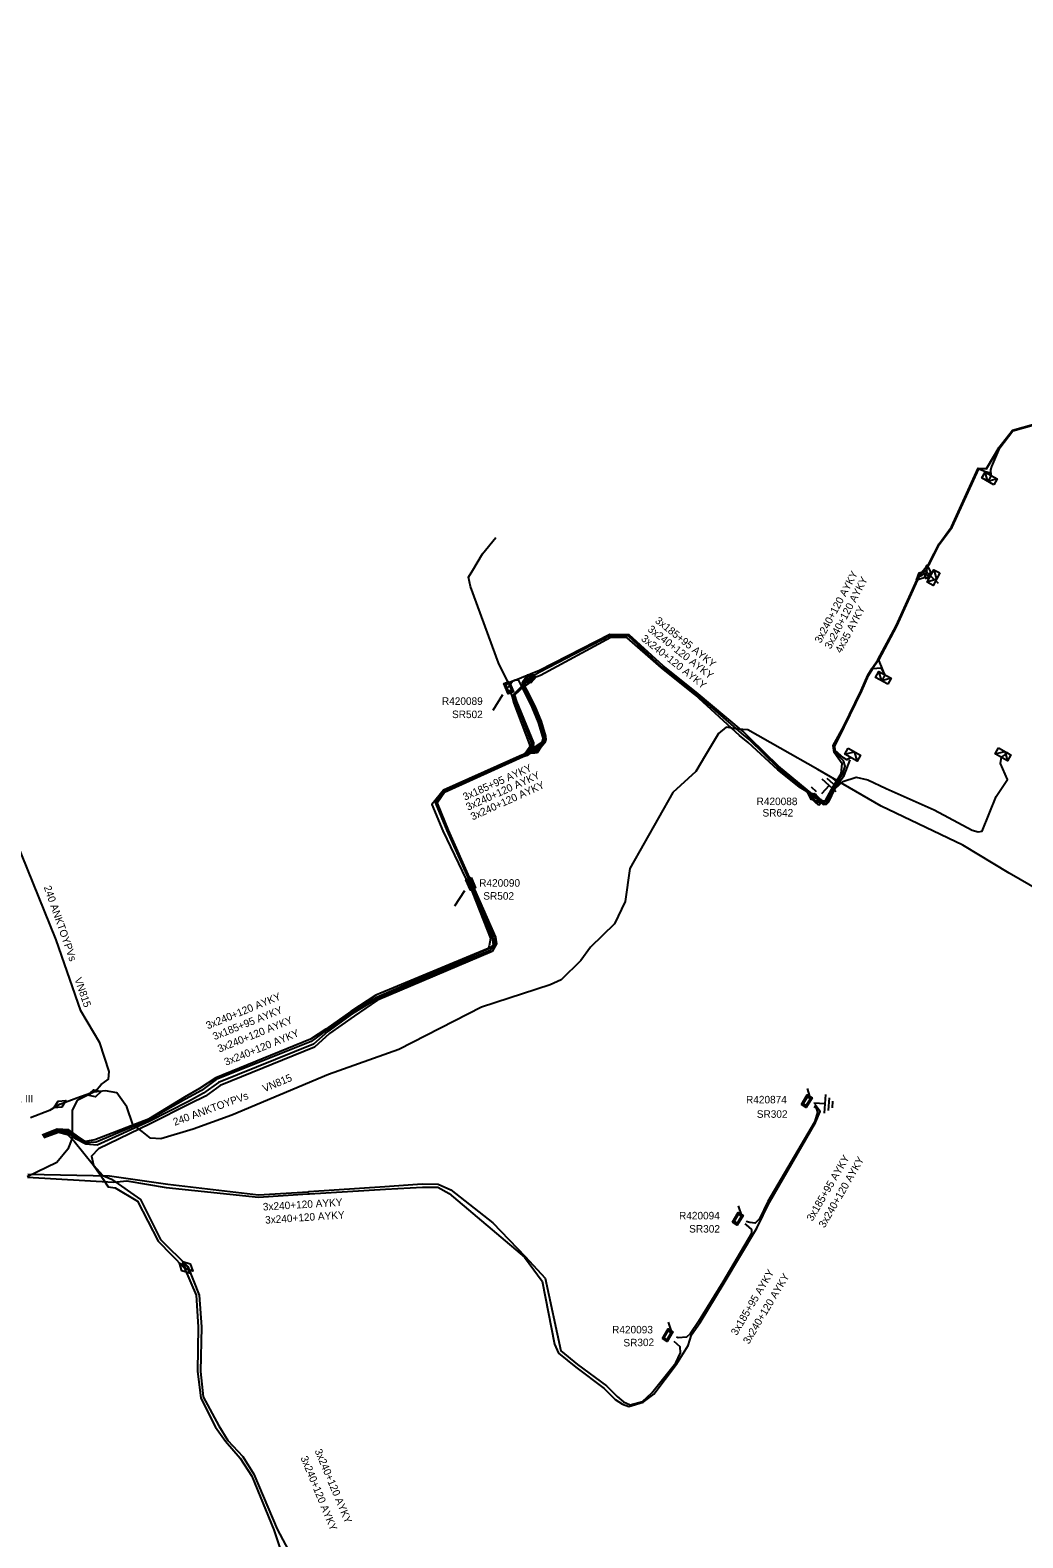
# Model space of a CAD drawing. Extents: x -540028 to -538776, y -1157064 to -1155670.
# Drawn here: x -539454.6 to -539322.6, y -1155928.9 to -1155728.4 of the extents above; entities that cross this region are included whole.
import ezdxf

# ---------------------------------------------------------------- set-up
doc = ezdxf.new("R2010")
doc.units = 0
for name, color, linetype in [('Vrstva 15', 7, 'Continuous'), ('Vrstva 19', 7, 'Continuous'), ('Vrstva 2', 7, 'Continuous'), ('Vrstva 27', 7, 'Continuous'), ('Vrstva 28', 7, 'Continuous'), ('Vrstva 29', 7, 'Continuous'), ('Vrstva 30', 7, 'Continuous'), ('Vrstva 31', 7, 'Continuous'), ('Vrstva 5', 7, 'Continuous'), ('Vrstva 52', 7, 'Continuous'), ('Vrstva 59', 7, 'Continuous'), ('Vrstva 6', 7, 'Continuous'), ('Vrstva 7', 7, 'Continuous'), ('Vrstva 9', 7, 'Continuous')]:
    doc.layers.add(name, color=color, linetype=linetype)

# ---------------------------------------------------------------- blocks, each defined once
blk = doc.blocks.new('17')
at = {"layer": 'Vrstva 2'}
blk.add_lwpolyline([(-1.875, 0), (0, 0.9375), (1.875, 0), (0, -0.9375)], close=True, dxfattribs=at)
blk = doc.blocks.new('132')
at = {"layer": 'Vrstva 2'}
for points in [[(-1.5, 1.5), (1.5, 1.5), (1.5, 0), (-1.5, 0)], [(-1.1, 1.2), (1.1, 1.2), (1.1, 0.3), (-1.1, 0.3)]]:
    blk.add_lwpolyline(points, close=True, dxfattribs=at)
blk = doc.blocks.new('23')
at = {"layer": 'Vrstva 2'}
blk.add_lwpolyline([(1.875, -1.8), (-1.875, -1.8), (-1.875, 0), (1.875, 0)], close=True, dxfattribs=at)
blk.add_lwpolyline([(1.875, 0), (0, -1.8), (-1.875, 0)], dxfattribs=at)
blk = doc.blocks.new('11')
at = {"layer": 'Vrstva 2'}
for p, q in [((0, -4.3), (0, -1.3)), ((-2.5, -4.3), (2.5, -4.3)), ((-1.7, -5.3), (1.7, -5.3)), ((-0.9, -6.3), (0.9, -6.3))]:
    blk.add_line(p, q, dxfattribs=at)

msp = doc.modelspace()

# ---------------------------------------------------------------- linework, layer by layer
at = {"layer": 'Vrstva 5'}
for points in [[(-539450.64, -1155871.22), (-539448.38, -1155870.37), (-539445.91, -1155869.51), (-539445.16, -1155868.63), (-539444.2, -1155867.88), (-539444.08, -1155866.88), (-539445.32, -1155863.06), (-539447.87, -1155858.8), (-539451.16, -1155849.36), (-539456.5, -1155836.11), (-539463.8, -1155817.93), (-539469.08, -1155806.9), (-539474.9, -1155790.51), (-539482.11, -1155775.46), (-539488.3, -1155760.82), (-539493.72, -1155747.89), (-539499.46, -1155736.84), (-539501.89, -1155728.36)], [(-539350.46, -1155830.35), (-539349.58, -1155830.73), (-539349.23, -1155830.93), (-539348.81, -1155830.82), (-539348.05, -1155829.35), (-539346.75, -1155827.26), (-539346.61, -1155825.96), (-539347.7, -1155824.44), (-539347.79, -1155823.53), (-539346.43, -1155821.03), (-539344.08, -1155816.21), (-539343.22, -1155814.17), (-539342.63, -1155813.23), (-539341.85, -1155812.12), (-539339.44, -1155807.59), (-539336.43, -1155800.94), (-539335.03, -1155799.25), (-539333.73, -1155796.7), (-539332.06, -1155794.44), (-539328.52, -1155786.63), (-539327.44, -1155786.68), (-539325.72, -1155783.84), (-539323.97, -1155781.59), (-539321.14, -1155780.78)], [(-539349.17, -1155830.8), (-539349.17, -1155830.84), (-539349, -1155831.04), (-539348.87, -1155831.01), (-539347.97, -1155829.36), (-539346.58, -1155827.35), (-539346.21, -1155826.25), (-539346.44, -1155825.57), (-539346.82, -1155825.15), (-539347.63, -1155824.37), (-539347.67, -1155823.56), (-539346.39, -1155821.05), (-539344.03, -1155816.24), (-539343.17, -1155814.19), (-539342.59, -1155813.26), (-539341.81, -1155812.15), (-539339.4, -1155807.61), (-539336.39, -1155800.97), (-539334.99, -1155799.28), (-539333.69, -1155796.73), (-539332.02, -1155794.47), (-539328.48, -1155786.68), (-539327.41, -1155786.73), (-539325.68, -1155783.87), (-539323.94, -1155781.64), (-539321.12, -1155780.82)], [(-539335.35, -1155800.45), (-539335.32, -1155799.75), (-539334.95, -1155799.31), (-539333.65, -1155796.75), (-539331.98, -1155794.49), (-539328.45, -1155786.73), (-539327.56, -1155787.08), (-539327.05, -1155787.19), (-539326.8, -1155787.6), (-539326.85, -1155786.84), (-539326.71, -1155786.39), (-539325.64, -1155783.9), (-539323.91, -1155781.68), (-539321.1, -1155780.87)], [(-539345.45, -1155825.13), (-539345.98, -1155825.42), (-539346.44, -1155825.18), (-539347.53, -1155824.18), (-539347.58, -1155823.6), (-539346.34, -1155821.07), (-539343.99, -1155816.26), (-539343.13, -1155814.22), (-539342.55, -1155813.29), (-539341.47, -1155813.2), (-539340.92, -1155814.12), (-539341.38, -1155813.02), (-539341.76, -1155812.18), (-539339.35, -1155807.63), (-539336.34, -1155800.99), (-539336.03, -1155800.89)], [(-539336.03, -1155800.89), (-539335.81, -1155800.7), (-539334.86, -1155800.96), (-539335.35, -1155800.45)], [(-539350.17, -1155830.06), (-539350.29, -1155830.09), (-539350.5, -1155830.02), (-539355.08, -1155826.25), (-539358.89, -1155822.53), (-539359.8, -1155821.67), (-539366.01, -1155816.43), (-539370.42, -1155812.91), (-539374.94, -1155808.8), (-539377.53, -1155808.75), (-539386.87, -1155813.56), (-539390.47, -1155814.99), (-539390.96, -1155815.66), (-539391.31, -1155815.93)], [(-539350.06, -1155830.15), (-539350.27, -1155830.21), (-539350.61, -1155830.16), (-539355.12, -1155826.47), (-539358.99, -1155822.71), (-539360.01, -1155821.86), (-539366.13, -1155816.57), (-539370.58, -1155813.08), (-539375.01, -1155808.97), (-539377.49, -1155808.93), (-539386.81, -1155813.78), (-539388.26, -1155814.55)], [(-539350.46, -1155830.35), (-539351.41, -1155829.57), (-539352.28, -1155829.08), (-539355.17, -1155826.74), (-539359.13, -1155823.11), (-539360.25, -1155822.19), (-539366.15, -1155816.77), (-539370.64, -1155813.2), (-539375.21, -1155809.19), (-539377.37, -1155809.14), (-539386.75, -1155814.19), (-539388.18, -1155814.73)], [(-539387.94, -1155824.06), (-539386.71, -1155823.21), (-539386.48, -1155822.94), (-539386.38, -1155822.64), (-539386.4, -1155822.37), (-539386.99, -1155820.48), (-539387.82, -1155818.43), (-539388.91, -1155816.28), (-539389.26, -1155815.6), (-539389.63, -1155814.88), (-539390.08, -1155814.81), (-539391.43, -1155815.38), (-539391.2, -1155816.18)], [(-539387.77, -1155824.15), (-539386.58, -1155823.36), (-539386.3, -1155823.04), (-539386.18, -1155822.67), (-539386.2, -1155822.33), (-539386.8, -1155820.41), (-539387.64, -1155818.35), (-539388.73, -1155816.19), (-539389.08, -1155815.51), (-539389.11, -1155815.09), (-539388.87, -1155814.81), (-539388.26, -1155814.55)], [(-539387.42, -1155824.07), (-539386.45, -1155823.51), (-539386.12, -1155823.14), (-539385.98, -1155822.7), (-539386, -1155822.29), (-539386.61, -1155820.34), (-539387.46, -1155818.27), (-539388.55, -1155816.1), (-539388.95, -1155815.32), (-539388.93, -1155815.17), (-539388.75, -1155814.97), (-539388.18, -1155814.73)], [(-539314.79, -1155846.05), (-539324.41, -1155840.48), (-539330.57, -1155836.78), (-539341.42, -1155831.6), (-539349.86, -1155826.71), (-539354.84, -1155823.88), (-539359.14, -1155821.43), (-539360.48, -1155821.33), (-539362.03, -1155821.08), (-539363.05, -1155821.91), (-539364.77, -1155824.8), (-539366.07, -1155826.96), (-539369.12, -1155829.77), (-539374.87, -1155839.9), (-539375.46, -1155844.26), (-539376.91, -1155847.22), (-539380.1, -1155850.36), (-539381.37, -1155852.1), (-539383.98, -1155854.67), (-539385.45, -1155855.37), (-539394.59, -1155858.34), (-539405.57, -1155863.94), (-539414.91, -1155867.28), (-539427.79, -1155872.68), (-539432.92, -1155874.55), (-539437.2, -1155875.84), (-539438.59, -1155875.77), (-539439.7, -1155874.86), (-539440.93, -1155873.95), (-539441.75, -1155871.58), (-539443.09, -1155869.72), (-539444.57, -1155869.47), (-539446.14, -1155869.63)], [(-539387.77, -1155824.15), (-539388.62, -1155824.67), (-539389.09, -1155824.87), (-539399.57, -1155829.62), (-539400.71, -1155831.18), (-539399.19, -1155834.82), (-539395.58, -1155842.86), (-539392.98, -1155849.03), (-539392.74, -1155849.96), (-539393.44, -1155850.79), (-539408.48, -1155857.21), (-539411.79, -1155859.23), (-539415.03, -1155861.58), (-539416.93, -1155863.25), (-539429.55, -1155868.34), (-539431.54, -1155869.77), (-539433.56, -1155870.87), (-539438.76, -1155873.53), (-539445.67, -1155876.69), (-539447.18, -1155876.55), (-539448.46, -1155875.9), (-539449.51, -1155875.09), (-539450.89, -1155874.8), (-539452.86, -1155875.56)], [(-539387.94, -1155824.06), (-539388.72, -1155824.5), (-539389.11, -1155824.74), (-539399.64, -1155829.45), (-539401.18, -1155831.35), (-539399.72, -1155834.88), (-539396.61, -1155841.35), (-539396.58, -1155841.48)], [(-539387.42, -1155824.07), (-539388.52, -1155824.84), (-539389.02, -1155825.03), (-539399.51, -1155829.78), (-539400.48, -1155831.19), (-539398.99, -1155834.79), (-539395.86, -1155841.89)], [(-539349.33, -1155830.76), (-539349.26, -1155831.05), (-539348.95, -1155831.28), (-539348.65, -1155831.17), (-539347.78, -1155829.42), (-539346.35, -1155827.51), (-539345.56, -1155825.42)], [(-539396.15, -1155842.49), (-539395.96, -1155842.66), (-539395.83, -1155842.97), (-539393.4, -1155849.2), (-539393.54, -1155850.15), (-539393.7, -1155850.5), (-539408.62, -1155856.73), (-539411.96, -1155858.9), (-539415.3, -1155861.26), (-539417.31, -1155862.58), (-539429.92, -1155867.72), (-539432.06, -1155869.16), (-539434.06, -1155870.29), (-539438.88, -1155873.23), (-539445.99, -1155875.96), (-539447.23, -1155876.18), (-539448.29, -1155875.49), (-539449.45, -1155874.63), (-539450.99, -1155874.53), (-539453, -1155875.33)], [(-539395.86, -1155841.89), (-539395.76, -1155842.59), (-539393.14, -1155849.05), (-539393.04, -1155850.05), (-539393.58, -1155850.57), (-539408.56, -1155857.02), (-539411.88, -1155859.03), (-539415.22, -1155861.43), (-539417.23, -1155862.88), (-539429.85, -1155867.93), (-539431.8, -1155869.43), (-539433.94, -1155870.58), (-539438.85, -1155873.36), (-539445.81, -1155876.26), (-539447.2, -1155876.38), (-539448.34, -1155875.72), (-539449.5, -1155874.86), (-539450.95, -1155874.64), (-539452.93, -1155875.46)], [(-539396.31, -1155842.12), (-539395.5, -1155842.69), (-539392.72, -1155849), (-539392.57, -1155849.91), (-539393.14, -1155850.9), (-539408.41, -1155857.4), (-539411.5, -1155859.54), (-539414.81, -1155861.81), (-539416.8, -1155863.63), (-539429.35, -1155868.75), (-539431.28, -1155870.18), (-539433.38, -1155871.2), (-539438.65, -1155873.86), (-539445.5, -1155877.17), (-539446.44, -1155878.16), (-539446.18, -1155879.34), (-539444.94, -1155880.73), (-539443.78, -1155881.19), (-539439.94, -1155883.89), (-539437.25, -1155889.23), (-539433.63, -1155892.8), (-539432.13, -1155896.62), (-539431.83, -1155900.84), (-539431.95, -1155906.78), (-539431.61, -1155910.16), (-539429.51, -1155914.02), (-539428.3, -1155915.97), (-539426.33, -1155918.09), (-539424.85, -1155920.45), (-539421.77, -1155927.78), (-539417.65, -1155935.45)], [(-539446.14, -1155869.63), (-539448.34, -1155870.73), (-539449.01, -1155872.03), (-539449.01, -1155875.77), (-539449.57, -1155877.23), (-539451.04, -1155879), (-539454.99, -1155880.88)], [(-539454.95, -1155880.92), (-539443.5, -1155881.62), (-539441.75, -1155881.42), (-539436.53, -1155882.31), (-539424.22, -1155883.58), (-539417.66, -1155883.14), (-539417.46, -1155883.14), (-539407.35, -1155882.52), (-539402.43, -1155882.27), (-539400.39, -1155882.26), (-539398.88, -1155883.11), (-539388.84, -1155891.58), (-539386.53, -1155894.75), (-539384.85, -1155903.15), (-539384.32, -1155904.34), (-539382.04, -1155906.21), (-539378.28, -1155909.05), (-539376.82, -1155910.51), (-539375.81, -1155911.15), (-539374.99, -1155911.45), (-539373.09, -1155910.88), (-539371.68, -1155909.81), (-539368.65, -1155905.83), (-539367.1, -1155903.31), (-539366.67, -1155901.89), (-539365.5, -1155900.26), (-539362.3, -1155895.01), (-539357.97, -1155887.74), (-539356.29, -1155884.27), (-539350.17, -1155873.67), (-539349.55, -1155872.19), (-539350.26, -1155871.29)], [(-539450.64, -1155871.22), (-539452.01, -1155872.05), (-539454.56, -1155873.05)], [(-539350.4, -1155871.52), (-539350.05, -1155871.76), (-539349.9, -1155872.31), (-539350.31, -1155873.6), (-539356.48, -1155884.17), (-539357.59, -1155886.47), (-539358.2, -1155887.06), (-539358.89, -1155886.95), (-539359.37, -1155886.83)], [(-539452.8, -1155875.66), (-539450.82, -1155874.95), (-539449.64, -1155875.25), (-539448.74, -1155876.15), (-539446.18, -1155879.34), (-539444.99, -1155881.07), (-539444.21, -1155882.24), (-539443.31, -1155882.35), (-539440.32, -1155884.14), (-539437.56, -1155889.45), (-539434.08, -1155893.05), (-539432.51, -1155896.62), (-539432.27, -1155900.84), (-539432.34, -1155906.73), (-539431.9, -1155910.33), (-539429.95, -1155914.18), (-539428.63, -1155916.07), (-539426.67, -1155918.3), (-539425.12, -1155920.72), (-539422.21, -1155927.83), (-539420.46, -1155932.98), (-539420.81, -1155933.39)], [(-539454.92, -1155880.55), (-539444.05, -1155880.76), (-539441.88, -1155881.08), (-539436.29, -1155881.88), (-539424.25, -1155883.3), (-539417.63, -1155882.91), (-539417.52, -1155882.86), (-539407.43, -1155882.17), (-539402.45, -1155881.81), (-539400.34, -1155881.86), (-539398.67, -1155882.63), (-539393.06, -1155887.02), (-539388.76, -1155891.48), (-539386.12, -1155894.39), (-539384.03, -1155904.04), (-539381.8, -1155905.84), (-539377.97, -1155908.69), (-539376.54, -1155910.11), (-539375.7, -1155910.84), (-539374.79, -1155911.23), (-539373.16, -1155910.76), (-539371.93, -1155909.63), (-539368.74, -1155905.65), (-539368.12, -1155904.3), (-539368.16, -1155903.49), (-539368.97, -1155902.78)], [(-539359.57, -1155887.16), (-539359.38, -1155887.27), (-539358.66, -1155887.88), (-539358.67, -1155888.45), (-539362.5, -1155894.92), (-539365.73, -1155900.12), (-539366.83, -1155901.78), (-539367.3, -1155902.2), (-539368.41, -1155902.29), (-539368.64, -1155902.24)]]:
    msp.add_lwpolyline(points, dxfattribs=at)
at = {"layer": 'Vrstva 52'}
for points in [[(-539391.41, -1155815.68), (-539391.01, -1155815.13), (-539392.33, -1155812.51), (-539396.03, -1155802.38), (-539396.3, -1155801.13), (-539395.75, -1155800.18), (-539394.45, -1155798.04), (-539392.69, -1155795.87)], [(-539349.49, -1155830.62), (-539349.45, -1155831.07), (-539349.15, -1155831.35), (-539348.71, -1155831.34), (-539348.39, -1155830.99), (-539347.53, -1155829.24), (-539346.52, -1155828.29), (-539344.75, -1155827.72), (-539343.19, -1155828.08), (-539340.76, -1155829.23), (-539334.39, -1155832.09), (-539329.34, -1155834.79), (-539328.53, -1155835.02), (-539327.99, -1155834.91), (-539326.15, -1155830.28), (-539324.62, -1155828.05), (-539325.58, -1155825.93), (-539325.43, -1155825.09)]]:
    msp.add_lwpolyline(points, dxfattribs=at)
at = {"layer": 'Vrstva 59'}
for points in [[(-539326.8, -1155787.6), (-539327.3, -1155788.47)], [(-539334.86, -1155800.96), (-539333.84, -1155801.94)], [(-539340.92, -1155814.12), (-539341.4, -1155814.99)], [(-539391.77, -1155816.79), (-539393.08, -1155818.85)], [(-539325.43, -1155825.09), (-539324.51, -1155824.45)], [(-539350.04, -1155829.69), (-539350.69, -1155829.08)], [(-539396.84, -1155842.83), (-539398.16, -1155844.9)], [(-539350.76, -1155870.61), (-539351.24, -1155869.15)], [(-539359.9, -1155886.19), (-539360.39, -1155884.73)], [(-539369.21, -1155901.69), (-539369.69, -1155900.23)]]:
    msp.add_lwpolyline(points, dxfattribs=at)
at = {"layer": 'Vrstva 9'}
for points in [[(-539388.49, -1155815.02), (-539389.09, -1155815.47), (-539390.41, -1155816.81), (-539390.05, -1155817.73), (-539387.93, -1155823.27), (-539387.93, -1155823.7)], [(-539388.26, -1155815.23), (-539388.99, -1155815.73), (-539390.2, -1155816.83), (-539389.92, -1155817.67), (-539387.66, -1155823.17), (-539387.7, -1155823.69)], [(-539391.01, -1155816.19), (-539390.76, -1155816.21), (-539390.66, -1155816.55), (-539390.51, -1155817.04), (-539390.27, -1155817.88), (-539388.19, -1155823.38), (-539388.16, -1155823.73)]]:
    msp.add_lwpolyline(points, dxfattribs=at)

# ---------------------------------------------------------------- block references
at = {"layer": 'Vrstva 15'}
for p, xscale, yscale, rotation in [((-539349.78, -1155830.42), 0.5, 0.5000000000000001, 137.60256209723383), ((-539351.01, -1155871.02), 0.5000000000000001, 0.5, 85.2694055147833)]:
    msp.add_blockref('11', p, dxfattribs=dict(at, xscale=xscale, yscale=yscale, rotation=rotation))
at = {"layer": 'Vrstva 19'}
for p, xscale, yscale, rotation in [((-539336.03, -1155800.89), 0.49999999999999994, 0.5000000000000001, 43.573329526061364), ((-539335.35, -1155800.45), 0.5, 0.5000000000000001, 87.17636066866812), ((-539388.26, -1155814.55), 0.5, 0.5, 27.84816104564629), ((-539388.18, -1155814.73), 0.49999999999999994, 0.5000000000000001, 20.787922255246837), ((-539387.94, -1155824.06), 0.5, 0.5000000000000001, 29.2466000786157), ((-539387.77, -1155824.15), 0.5, 0.49999999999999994, 31.456822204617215), ((-539387.42, -1155824.07), 0.5, 0.5000000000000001, 29.246600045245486), ((-539350.46, -1155830.35), 0.5, 0.5, 140.61220328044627), ((-539446.05, -1155869.79), 0.5, 0.5000000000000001, 15.59280007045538), ((-539450.64, -1155871.22), 0.5, 0.5000000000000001, 31.20913340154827), ((-539434.08, -1155893.05), 0.5, 0.49999999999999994, -45.987480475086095), ((-539433.63, -1155892.8), 0.49999999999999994, 0.5000000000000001, -44.545472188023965)]:
    msp.add_blockref('17', p, dxfattribs=dict(at, xscale=xscale, yscale=yscale, rotation=rotation))
at = {"layer": 'Vrstva 28'}
for p, xscale, yscale, rotation in [((-539391.31, -1155815.97), 0.5, 0.5, -66.8731750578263), ((-539349.78, -1155830.42), 0.49999999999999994, 0.5000000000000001, 137.58084523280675), ((-539396.35, -1155842.08), 0.5, 0.5, -66.65494166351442), ((-539351, -1155871.02), 0.5000000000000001, 0.5, 58.88096660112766), ((-539360.18, -1155886.66), 0.49999999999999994, 0.5000000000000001, 59.17457223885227), ((-539369.5, -1155902.16), 0.5, 0.5, 59.11408891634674)]:
    msp.add_blockref('132', p, dxfattribs=dict(at, xscale=xscale, yscale=yscale, rotation=rotation))
at = {"layer": 'Vrstva 31'}
for p, xscale, yscale, rotation in [((-539326.8, -1155787.6), 0.49999999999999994, 0.5, -29.613277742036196), ((-539334.86, -1155800.96), 0.5, 0.5, 61.27296255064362), ((-539340.92, -1155814.12), 0.5000000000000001, 0.4999999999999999, -28.948969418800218), ((-539345.45, -1155825.13), 0.5, 0.5, 150.46851106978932), ((-539325.43, -1155825.09), 0.5000000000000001, 0.5, 151.08402494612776)]:
    msp.add_blockref('23', p, dxfattribs=dict(at, xscale=xscale, yscale=yscale, rotation=rotation))

# ---------------------------------------------------------------- texts
at = {"layer": 'Vrstva 27'}
msp.add_text('T19 OSKOL III', height=1, dxfattribs=at).set_placement((-539462.95, -1155871))
at = {"layer": 'Vrstva 29'}
for s, p in [('R420089', (-539399.84, -1155818.11)), ('R420088', (-539357.99, -1155831.45)), ('R420090', (-539394.88, -1155842.3)), ('R420874', (-539359.4, -1155871.12)), ('R420094', (-539368.31, -1155886.55)), ('R420093', (-539377.21, -1155901.72))]:
    msp.add_text(s, height=1, dxfattribs=at).set_placement(p)
at = {"layer": 'Vrstva 30'}
for s, rotation, p in [('SR502', 359.902, (-539398.5, -1155819.87)), ('SR642', 0.058, (-539357.21, -1155832.97)), ('SR502', 359.82, (-539394.34, -1155844.02)), ('SR302', 359.986, (-539357.97, -1155873.04)), ('SR302', 359.786, (-539366.96, -1155888.3)), ('SR302', 0.958, (-539375.7, -1155903.46))]:
    msp.add_text(s, height=1, rotation=rotation, dxfattribs=at).set_placement(p)
at = {"layer": 'Vrstva 6'}
for s, rotation, p in [('3x240+120 AYKY', 62.017, (-539349.46, -1155809.99)), ('3x240+120 AYKY', 62.019, (-539348.15, -1155810.77)), ('4x35 AYKY', 62.02, (-539346.74, -1155811.32)), ('3x185+95 AYKY', 321.399, (-539371.58, -1155807.08)), ('3x240+120 AYKY', 321.466, (-539373.44, -1155809.46)), ('3x240+120 AYKY', 321.858, (-539372.56, -1155808.22)), ('3x185+95 AYKY', 24.128, (-539396.78, -1155830.86)), ('3x240+120 AYKY', 24.404, (-539396.37, -1155832.2)), ('3x240+120 AYKY', 24.365, (-539395.75, -1155833.49)), ('240 ANKTOYPVs', 289.264, (-539452.8, -1155842.36)), ('3x240+120 AYKY', 22.167, (-539430.97, -1155861.28)), ('3x185+95 AYKY', 21.789, (-539430.09, -1155862.72)), ('3x240+120 AYKY', 21.985, (-539429.43, -1155864.37)), ('3x240+120 AYKY', 22.165, (-539428.55, -1155866.13)), ('240 ANKTOYPVs', 20.065, (-539435.38, -1155874.11)), ('3x185+95 AYKY', 59.712, (-539350.56, -1155886.88)), ('3x240+120 AYKY', 60.002, (-539348.95, -1155887.76)), ('3x240+120 AYKY', 3.414, (-539423.62, -1155885.38)), ('3x240+120 AYKY', 3.838, (-539423.32, -1155887.13)), ('3x185+95 AYKY', 59.408, (-539360.63, -1155902.07)), ('3x240+120 AYKY', 59.203, (-539359.02, -1155903.23)), ('3x240+120 AYKY', 292.775, (-539416.79, -1155917.33)), ('3x240+120 AYKY', 292.246, (-539418.66, -1155918.26))]:
    msp.add_text(s, height=1, rotation=rotation, dxfattribs=at).set_placement(p)
at = {"layer": 'Vrstva 7'}
for rotation, p in [(289.264, (-539448.73, -1155854.58)), (22.75, (-539423.44, -1155869.66))]:
    msp.add_text('VN815', height=1, rotation=rotation, dxfattribs=at).set_placement(p)

doc.saveas('drawing.dxf')
